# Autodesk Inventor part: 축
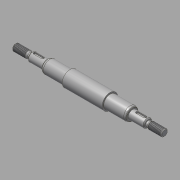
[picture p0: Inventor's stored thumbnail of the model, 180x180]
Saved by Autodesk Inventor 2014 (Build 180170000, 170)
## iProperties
Created: 2015-11
Part Number: 축
Material: 강철, 연강
Document SubType Name: Modeling
Designer: mduedu
Density: 7.86 g/cm^3
Mass: 198.507 g
Surface Area: 75.8873 cm^2
Volume: 25.2553 cm^3
Appearance: 강철
Author: mduedu
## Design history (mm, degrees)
sketch "스케치1"
  geometry: L1 (-86, 0)-(86, 0); L2 (-86, 0)-(-86, 4); L3 (-86, 4)-(-70.732, 4); L4 (-70.732, 4)-(-69, 3); L5 (-69, 3)-(-67, 3); L6 (-67, 3)-(-67, 5); L7 (-67, 5)-(-49, 5); L8 (-49, 5)-(-49, 6.55); L9 (-47.355, 7.5)-(-23, 7.5); L10 (-23, 7.5)-(-23, 9); L11 (0, 0)-(0, 9); L12 (86, 4)-(70.732, 4); L13 (70.732, 4)-(69, 3); L14 (69, 3)-(67, 3); L15 (67, 3)-(67, 5); L16 (67, 5)-(49, 5); L17 (23, 7.5)-(23, 9); L18 (86, 0)-(86, 4); L19 (-23, 9)-(23, 9); L20 (-49, 6.55)-(-47.355, 7.5); L21 (47.355, 7.5)-(23, 7.5); L22 (49, 6.55)-(47.355, 7.5); L23 (49, 5)-(49, 6.55); 1 further point
  constraints: 46 end point, 10 symmetric about line, 6 perpendicular, 5 parallel, 2 midpoint, 1 coincident, 1 horizontal
  dimensions: "d0" = 172 distance of L1.start L1.end (derived); "d1" = 8 diameter of L3 L1; "d2" = 30 deg angle of L4 L5; "d3" = 6 diameter of L5 L1; "d4" = 10 diameter of L7 L1; "d5" = 15 diameter of L9 L1; "d6" = 18 diameter of L19 L1; "d8" = 18 distance of L6.end L7.end; "d9" = 46 distance of L10.end L17.end; "d10" = 2 distance of L4.end L5.end; "d11" = 17 distance from line of L4.end L2; "d16" = 13.1 diameter of L8.end L1; "d17" = 30 deg angle of L20 L9; "d18" = 26 distance between parallel lines of L10 L8
revolve "회전1" sketch "스케치1" stored, may be unused: angle "d12" = 90 deg
chamfer "모따기1" distance "d13" = 1; stored, may be unused: second distance "d14" = 2, angle "d15" = 45 deg
fillet "모깎기1" dims "d19" = 4, "d20" = 0.5
node "작업 평면1"
sketch "스케치2" dims "d23" = 12
  geometry: L1 (-5.5, 1.5)-(3.5, 1.5); L2 (3.5, 1.5)-(3.5, -1.5); L3 (3.5, -1.5)-(-5.5, -1.5); L4 (-5.5, -1.5)-(-5.5, 1.5); L5 (-9, -4)-(-9, 4) reference; 3 further points
  constraints: 8 end point, 2 midpoint, 2 parallel, 2 vertical alignment, 1 horizontal, 1 perpendicular, 4 other
  dimensions: "d21" = 3 distance between parallel lines of L3 L1; "d24" = 2 dimension on L5
extrude "돌출1" cut sketch "스케치2" distance "d25" = 1.8; taper "d26" = 0 deg
feature "스레드1" dims "d27" = 10, "d28" = 0
feature "스레드2" dims "d29" = 10, "d30" = 0
chamfer "모따기2" distance "d31" = 1; stored, may be unused: second distance "d32" = 2, angle "d33" = 45 deg
fillet "모깎기2" dims "d34" = 0.3
node "솔리드1"
mirror "대칭1"
